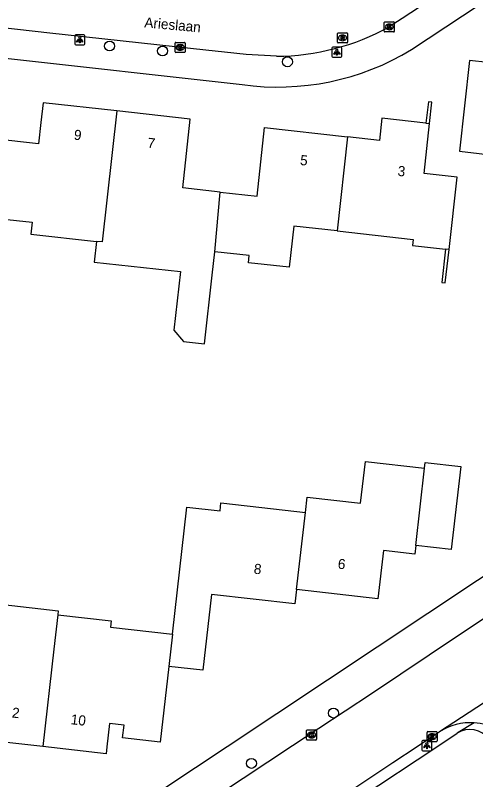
# Model space of a CAD drawing. Extents: x 162398 to 163643, y 386453 to 387397.
# Drawn here: x 163009.8 to 163055.2, y 386746.7 to 386822.3 of the extents above; entities that cross this region are included whole.
import ezdxf

# ---------------------------------------------------------------- set-up
doc = ezdxf.new("R2010")
doc.units = 0
for name, color, linetype in [('IMGEO_Boom', 7, 'Continuous'), ('IMGEO_Kolk', 7, 'Continuous'), ('IMGEO_Lichtpunt', 7, 'Continuous'), ('IMGEO_Muur', 7, 'Continuous'), ('IMGEO_Openbare_ruimte_label', 7, 'Continuous'), ('IMGEO_Pand', 7, 'Continuous'), ('IMGEO_Pand_nummerreeks', 7, 'Continuous'), ('IMGEO_Rijbaan_lokaal_gesloten', 7, 'Continuous'), ('IMGEO_Rijbaan_lokaal_open', 7, 'Continuous'), ('IMGEO_Rioolput', 7, 'Continuous'), ('IMGEO_Voetpad_open', 7, 'Continuous')]:
    doc.layers.add(name, color=color, linetype=linetype)

msp = doc.modelspace()

# ---------------------------------------------------------------- linework, layer by layer
at = {"layer": 'IMGEO_Boom'}
for centre in [(163019.068, 386819.272), (163024.298, 386818.785), (163036.636, 386817.714), (163041.181, 386753.326), (163033.082, 386748.352)]:
    msp.add_circle(centre, 0.489, dxfattribs=at)
at = {"layer": 'IMGEO_Kolk'}
for p, q in [((163046.192, 386820.738), (163046.192, 386821.59)), ((163046.267, 386821.664), (163047.119, 386821.664)), ((163046.68, 386821.444), (163046.705, 386821.444)), ((163047.193, 386821.59), (163047.193, 386820.738)), ((163047.119, 386820.664), (163046.267, 386820.664)), ((163046.703, 386820.884), (163046.678, 386820.884)), ((163025.537, 386818.707), (163025.537, 386819.559)), ((163025.612, 386819.633), (163026.464, 386819.633)), ((163026.025, 386819.413), (163026.05, 386819.413)), ((163026.538, 386819.559), (163026.538, 386818.707)), ((163026.048, 386818.853), (163026.023, 386818.853)), ((163026.464, 386818.633), (163025.612, 386818.633)), ((163038.52, 386750.737), (163038.52, 386751.589)), ((163038.595, 386751.663), (163039.447, 386751.663)), ((163039.008, 386751.443), (163039.033, 386751.443)), ((163039.521, 386751.589), (163039.521, 386750.737)), ((163050.426, 386750.569), (163050.426, 386751.421)), ((163050.501, 386751.495), (163051.353, 386751.495)), ((163051.427, 386751.421), (163051.427, 386750.569)), ((163039.447, 386750.663), (163038.595, 386750.663)), ((163039.031, 386750.883), (163039.006, 386750.883)), ((163050.937, 386750.715), (163050.912, 386750.715)), ((163050.914, 386751.275), (163050.939, 386751.275)), ((163051.353, 386750.495), (163050.501, 386750.495))]:
    msp.add_line(p, q, dxfattribs=at)
for points in [[(163046.192, 386820.738), (163046.192, 386821.59)], [(163046.267, 386821.664), (163047.119, 386821.664)], [(163046.513, 386821.364), (163046.636, 386821.364), (163046.636, 386821.213), (163046.766, 386821.364), (163046.93, 386821.364), (163046.784, 386821.213), (163046.937, 386820.964), (163046.785, 386820.964), (163046.7, 386821.128), (163046.636, 386821.061), (163046.636, 386820.964), (163046.513, 386820.964), (163046.513, 386821.364)], [(163047.193, 386821.59), (163047.193, 386820.738)], [(163047.119, 386820.664), (163046.267, 386820.664)], [(163025.537, 386818.707), (163025.537, 386819.559)], [(163025.612, 386819.633), (163026.464, 386819.633)], [(163026.538, 386819.559), (163026.538, 386818.707)], [(163025.858, 386819.333), (163025.981, 386819.333), (163025.981, 386819.182), (163026.111, 386819.333), (163026.275, 386819.333), (163026.129, 386819.182), (163026.282, 386818.933), (163026.13, 386818.933), (163026.045, 386819.097), (163025.981, 386819.03), (163025.981, 386818.933), (163025.858, 386818.933), (163025.858, 386819.333)], [(163026.464, 386818.633), (163025.612, 386818.633)], [(163038.52, 386750.737), (163038.52, 386751.589)], [(163038.595, 386751.663), (163039.447, 386751.663)], [(163039.521, 386751.589), (163039.521, 386750.737)], [(163050.426, 386750.569), (163050.426, 386751.421)], [(163050.501, 386751.495), (163051.353, 386751.495)], [(163051.427, 386751.421), (163051.427, 386750.569)], [(163039.447, 386750.663), (163038.595, 386750.663)], [(163038.841, 386751.363), (163038.964, 386751.363), (163038.964, 386751.212), (163039.094, 386751.363), (163039.258, 386751.363), (163039.112, 386751.212), (163039.265, 386750.963), (163039.113, 386750.963), (163039.028, 386751.127), (163038.964, 386751.06), (163038.964, 386750.963), (163038.841, 386750.963), (163038.841, 386751.363)], [(163050.747, 386751.195), (163050.87, 386751.195), (163050.87, 386751.044), (163051, 386751.195), (163051.164, 386751.195), (163051.018, 386751.044), (163051.171, 386750.795), (163051.019, 386750.795), (163050.934, 386750.959), (163050.87, 386750.892), (163050.87, 386750.795), (163050.747, 386750.795), (163050.747, 386751.195)], [(163051.353, 386750.495), (163050.501, 386750.495)]]:
    msp.add_lwpolyline(points, dxfattribs=at)
for centre, start, end in [((163046.269, 386821.588), 91.55205, 178.44795), ((163046.269, 386821.588), 91.55205, 178.44795), ((163047.117, 386821.588), 1.55205, 88.44795), ((163047.117, 386821.588), 1.55205, 88.44795), ((163046.269, 386820.74), 181.55205, 268.44795), ((163046.269, 386820.74), 181.55205, 268.44795), ((163047.117, 386820.74), 271.55205, 358.44795), ((163047.117, 386820.74), 271.55205, 358.44795), ((163025.614, 386819.557), 91.55205, 178.44795), ((163025.614, 386819.557), 91.55205, 178.44795), ((163026.462, 386819.557), 1.55205, 88.44795), ((163026.462, 386819.557), 1.55205, 88.44795), ((163025.614, 386818.709), 181.55205, 268.44795), ((163025.614, 386818.709), 181.55205, 268.44795), ((163026.462, 386818.709), 271.55205, 358.44795), ((163026.462, 386818.709), 271.55205, 358.44795), ((163038.597, 386751.587), 91.55205, 178.44795), ((163038.597, 386751.587), 91.55205, 178.44795), ((163039.445, 386751.587), 1.55205, 88.44795), ((163039.445, 386751.587), 1.55205, 88.44795), ((163050.503, 386751.419), 91.55205, 178.44795), ((163050.503, 386751.419), 91.55205, 178.44795), ((163051.351, 386751.419), 1.55205, 88.44795), ((163051.351, 386751.419), 1.55205, 88.44795), ((163038.597, 386750.739), 181.55205, 268.44795), ((163038.597, 386750.739), 181.55205, 268.44795), ((163039.445, 386750.739), 271.55205, 358.44795), ((163039.445, 386750.739), 271.55205, 358.44795), ((163050.503, 386750.571), 181.55205, 268.44795), ((163050.503, 386750.571), 181.55205, 268.44795), ((163051.351, 386750.571), 271.55205, 358.44795), ((163051.351, 386750.571), 271.55205, 358.44795)]:
    msp.add_arc(centre, 0.0765, start, end, dxfattribs=at)
for centre, major_axis, ratio, start_param, end_param in [((163046.679, 386821.164), (-0.387, 0.002), 0.722429, 4.712389, 7.853982), ((163046.704, 386821.164), (-0.39, 0.002), 0.717154, 1.570796, 4.712389), ((163026.024, 386819.133), (-0.387, 0.002), 0.722429, 4.712389, 7.853982), ((163026.049, 386819.133), (-0.39, 0.002), 0.717154, 1.570796, 4.712389), ((163039.007, 386751.163), (-0.387, 0.002), 0.722429, 4.712389, 7.853982), ((163039.032, 386751.163), (-0.39, 0.002), 0.717154, 1.570796, 4.712389), ((163050.913, 386750.995), (-0.387, 0.002), 0.722429, 4.712389, 7.853982), ((163050.938, 386750.995), (-0.39, 0.002), 0.717154, 1.570796, 4.712389)]:
    msp.add_ellipse(centre, major_axis=major_axis, ratio=ratio, start_param=start_param, end_param=end_param, dxfattribs=at)
at = {"layer": 'IMGEO_Lichtpunt'}
for p, q in [((163015.629, 386820.287), (163015.629, 386819.48)), ((163015.629, 386820.287), (163015.629, 386819.48)), ((163016.531, 386820.382), (163015.723, 386820.382)), ((163016.531, 386820.382), (163015.723, 386820.382)), ((163016.625, 386819.48), (163016.625, 386820.287)), ((163016.625, 386819.48), (163016.625, 386820.287)), ((163015.723, 386819.386), (163016.531, 386819.386)), ((163015.723, 386819.386), (163016.531, 386819.386)), ((163041.017, 386819.068), (163041.017, 386818.261)), ((163041.017, 386819.068), (163041.017, 386818.261)), ((163041.919, 386819.163), (163041.111, 386819.163)), ((163041.919, 386819.163), (163041.111, 386819.163)), ((163042.013, 386818.261), (163042.013, 386819.068)), ((163042.013, 386818.261), (163042.013, 386819.068)), ((163041.111, 386818.167), (163041.919, 386818.167)), ((163041.111, 386818.167), (163041.919, 386818.167)), ((163049.911, 386750.508), (163049.911, 386749.701)), ((163049.911, 386750.508), (163049.911, 386749.701)), ((163050.813, 386750.603), (163050.005, 386750.603)), ((163050.813, 386750.603), (163050.005, 386750.603)), ((163050.907, 386749.701), (163050.907, 386750.508)), ((163050.907, 386749.701), (163050.907, 386750.508)), ((163050.005, 386749.607), (163050.813, 386749.607)), ((163050.005, 386749.607), (163050.813, 386749.607))]:
    msp.add_line(p, q, dxfattribs=at)
for points in [[(163016.003, 386819.951), (163016.042, 386819.923), (163015.854, 386819.661), (163015.816, 386819.688), (163016.003, 386819.951)], [(163016.105, 386819.903), (163016.152, 386819.903), (163016.152, 386819.581), (163016.105, 386819.581), (163016.105, 386819.903)], [(163016.215, 386819.923), (163016.253, 386819.95), (163016.44, 386819.688), (163016.401, 386819.66), (163016.215, 386819.923)], [(163041.391, 386818.732), (163041.43, 386818.704), (163041.242, 386818.442), (163041.204, 386818.469), (163041.391, 386818.732)], [(163041.493, 386818.684), (163041.54, 386818.684), (163041.54, 386818.362), (163041.493, 386818.362), (163041.493, 386818.684)], [(163041.603, 386818.704), (163041.641, 386818.731), (163041.828, 386818.469), (163041.789, 386818.441), (163041.603, 386818.704)], [(163050.285, 386750.172), (163050.324, 386750.144), (163050.136, 386749.882), (163050.098, 386749.909), (163050.285, 386750.172)], [(163050.387, 386750.124), (163050.434, 386750.124), (163050.434, 386749.802), (163050.387, 386749.802), (163050.387, 386750.124)], [(163050.497, 386750.144), (163050.535, 386750.171), (163050.722, 386749.909), (163050.683, 386749.881), (163050.497, 386750.144)]]:
    msp.add_lwpolyline(points, dxfattribs=at)
for centre in [(163016.128, 386820.085), (163041.516, 386818.866), (163050.41, 386750.306)]:
    msp.add_circle(centre, 0.0994, dxfattribs=at)
for centre, start, end in [((163015.723, 386820.287), 90, 180), ((163015.723, 386820.287), 90, 180), ((163016.531, 386820.287), 0, 90), ((163016.531, 386820.287), 0, 90), ((163015.723, 386819.48), 180, 270), ((163015.723, 386819.48), 180, 270), ((163016.531, 386819.48), 270, 0), ((163016.531, 386819.48), 270, 360), ((163041.111, 386819.068), 90, 180), ((163041.111, 386819.068), 90, 180), ((163041.919, 386819.068), 0, 90), ((163041.919, 386819.068), 0, 90), ((163041.111, 386818.261), 180, 270), ((163041.111, 386818.261), 180, 270), ((163041.919, 386818.261), 270, 0), ((163041.919, 386818.261), 270, 360), ((163050.005, 386750.508), 90, 180), ((163050.005, 386750.508), 90, 180), ((163050.813, 386750.508), 0, 90), ((163050.813, 386750.508), 0, 90), ((163050.005, 386749.701), 180, 270), ((163050.005, 386749.701), 180, 270), ((163050.813, 386749.701), 270, 0), ((163050.813, 386749.701), 270, 360)]:
    msp.add_arc(centre, 0.0946, start, end, dxfattribs=at)
at = {"layer": 'IMGEO_Muur'}
for points in [[(163050.672, 386811.602), (163050.908, 386813.721), (163050.555, 386813.76), (163050.319, 386811.641)], [(163052.257, 386799.205), (163051.89, 386795.908), (163052.226, 386795.871), (163052.593, 386799.168)]]:
    msp.add_lwpolyline(points, dxfattribs=at)
at = {"layer": 'IMGEO_Pand'}
for points in [[(163066.327, 386819.722), (163058.593, 386820.582), (163058.245, 386817.455), (163054.632, 386817.856), (163054.132, 386813.363), (163053.632, 386808.864), (163057.516, 386808.432), (163057.789, 386810.893), (163065.254, 386810.063)], [(163019.775, 386812.85), (163012.505, 386813.659), (163012.288, 386811.705), (163012.052, 386809.588), (163007.606, 386810.082), (163007.27, 386807.057)], [(163019.775, 386812.85), (163018.332, 386799.903), (163017.79, 386799.963)], [(163030.005, 386804.84), (163026.29, 386805.253), (163027.045, 386812.042), (163019.775, 386812.85)], [(163050.319, 386811.641), (163045.955, 386812.126), (163045.712, 386809.946), (163042.58, 386810.294)], [(163030.005, 386804.84), (163033.631, 386804.437), (163034.384, 386811.205), (163042.58, 386810.294)], [(163052.593, 386799.168), (163053.388, 386806.32), (163050.125, 386806.683), (163050.672, 386811.602)], [(163050.319, 386811.641), (163050.672, 386811.602)], [(163042.58, 386810.294), (163041.544, 386800.986)], [(163029.462, 386798.929), (163030.005, 386804.84)], [(163006.748, 386802.369), (163011.436, 386801.848), (163011.307, 386800.683), (163017.79, 386799.963)], [(163041.544, 386800.986), (163037.264, 386801.462), (163036.812, 386797.398), (163032.789, 386797.846), (163032.867, 386798.55), (163029.462, 386798.929)], [(163041.544, 386800.986), (163049.062, 386800.15), (163048.997, 386799.567), (163052.257, 386799.205)], [(163017.79, 386799.963), (163017.563, 386797.918), (163026.073, 386796.972), (163025.428, 386791.171), (163026.374, 386790.071), (163028.451, 386789.84), (163029.206, 386796.623), (163029.462, 386798.929)], [(163052.593, 386799.168), (163052.257, 386799.205)], [(163038.409, 386773.163), (163038.581, 386774.671), (163043.866, 386774.067), (163044.339, 386778.203), (163050.183, 386777.535)], [(163050.183, 386777.535), (163050.247, 386778.097), (163053.753, 386777.697), (163052.816, 386769.493), (163049.306, 386769.894)], [(163049.306, 386769.894), (163050.183, 386777.535)], [(163025.28, 386761.115), (163026.716, 386773.684), (163029.982, 386773.311), (163030.074, 386774.115), (163035.259, 386773.523), (163038.409, 386773.163)], [(163037.541, 386765.536), (163038.409, 386773.163)], [(163049.306, 386769.894), (163049.208, 386769.033), (163046.119, 386769.385), (163045.574, 386764.618), (163037.541, 386765.536)], [(163037.541, 386765.536), (163037.378, 386764.113), (163029.133, 386765.055), (163028.276, 386757.554), (163024.923, 386757.937)], [(163012.47, 386750.008), (163006.213, 386750.723), (163006.545, 386753.632), (163001.291, 386754.232), (163001.859, 386759.2), (163002.375, 386763.72), (163008.45, 386763.025), (163008.567, 386764.05), (163014.004, 386763.429), (163013.961, 386763.046)], [(163013.961, 386763.046), (163013.572, 386759.652), (163012.47, 386750.008)], [(163013.961, 386763.046), (163019.238, 386762.443), (163019.166, 386761.814), (163025.28, 386761.115)], [(163025.28, 386761.115), (163024.923, 386757.937)], [(163024.923, 386757.937), (163024.067, 386750.448), (163020.358, 386750.871), (163020.501, 386752.127), (163019.068, 386752.291), (163018.806, 386750), (163018.725, 386749.294), (163012.47, 386750.008)]]:
    msp.add_lwpolyline(points, dxfattribs=at)
at = {"layer": 'IMGEO_Rijbaan_lokaal_gesloten'}
for points in [[(163018.704, 386737.897), (163020.532, 386739.148), (163021.049, 386739.492), (163022.823, 386740.671), (163027.385, 386743.673), (163037.12, 386750.107), (163044.946, 386755.247), (163053.527, 386761.018), (163084.016, 386781.282)], [(163065.539, 386760.542), (163051.663, 386751.486)], [(163051.663, 386751.486), (163051.609, 386751.451), (163051.556, 386751.416), (163049.437, 386750), (163047.031, 386748.398), (163043.288, 386745.904), (163024.659, 386733.665), (163022.574, 386732.192)]]:
    msp.add_lwpolyline(points, dxfattribs=at)
at = {"layer": 'IMGEO_Rijbaan_lokaal_open'}
for points in [[(163063.954, 386832.5), (163059.032, 386829.268), (163055.219, 386826.764), (163052.249, 386824.813), (163047.956, 386821.995), (163046.696, 386821.167)], [(163035.545, 386818.259), (163032.562, 386818.421), (163027.362, 386818.989), (163013.168, 386820.54), (163004.709, 386821.506)]]:
    msp.add_lwpolyline(points, dxfattribs=at)
for centre, radius, start, end in [((163035.335, 386841.898), 23.64, 270.50883, 298.72371), ((163054.725, 386746.675), 5.703, 86.3569, 122.47029), ((163054.72, 386746.67), 5.708, 39.54324, 86.30859)]:
    msp.add_arc(centre, radius, start, end, dxfattribs=at)
at = {"layer": 'IMGEO_Rioolput'}
for p, q in [((163041.577, 386819.654), (163041.577, 386820.506)), ((163041.652, 386820.58), (163042.504, 386820.58)), ((163042.065, 386820.36), (163042.09, 386820.36)), ((163042.578, 386820.506), (163042.578, 386819.654)), ((163042.504, 386819.58), (163041.652, 386819.58)), ((163042.088, 386819.8), (163042.063, 386819.8))]:
    msp.add_line(p, q, dxfattribs=at)
for points in [[(163041.577, 386819.654), (163041.577, 386820.506)], [(163041.652, 386820.58), (163042.504, 386820.58)], [(163042.166, 386820.278), (163041.914, 386820.28), (163041.914, 386819.88)], [(163042.092, 386820.199), (163042.038, 386820.199), (163042.038, 386820.118)], [(163042.578, 386820.506), (163042.578, 386819.654)], [(163042.504, 386819.58), (163041.652, 386819.58)], [(163041.914, 386819.88), (163042.038, 386819.88), (163042.038, 386820.042), (163042.049, 386820.042)], [(163042.038, 386820.118), (163042.09, 386820.118)], [(163042.096, 386820.013), (163042.167, 386819.88), (163042.307, 386819.88), (163042.242, 386820.006)]]:
    msp.add_lwpolyline(points, dxfattribs=at)
for centre, radius, start, end in [((163041.654, 386820.504), 0.0765, 91.55205, 178.44795), ((163041.654, 386820.504), 0.0765, 91.55205, 178.44795), ((163042.098, 386820.103), 0.0964, 77.00612, 93.18647), ((163042.112, 386820.16), 0.0378, 276.66336, 79.67722), ((163042.165, 386820.168), 0.109, 350.36119, 89.41601), ((163042.502, 386820.504), 0.0765, 1.55205, 88.44795), ((163042.502, 386820.504), 0.0765, 1.55205, 88.44795), ((163041.654, 386819.656), 0.0765, 181.55205, 268.44795), ((163041.654, 386819.656), 0.0765, 181.55205, 268.44795), ((163042.048, 386819.989), 0.0533, 26.02933, 88.69889), ((163042.074, 386820.307), 0.19, 274.7715, 282.96867), ((163042.163, 386820.168), 0.112, 277.58423, 350.98172), ((163042.147, 386819.953), 0.108, 29.51342, 73.79051), ((163042.502, 386819.656), 0.0765, 271.55205, 358.44795), ((163042.502, 386819.656), 0.0765, 271.55205, 358.44795)]:
    msp.add_arc(centre, radius, start, end, dxfattribs=at)
for centre, major_axis, ratio, start_param, end_param in [((163042.064, 386820.08), (-0.387, 0.002), 0.722429, 4.712389, 7.853982), ((163042.089, 386820.08), (-0.39, 0.002), 0.717154, 1.570796, 4.712389)]:
    msp.add_ellipse(centre, major_axis=major_axis, ratio=ratio, start_param=start_param, end_param=end_param, dxfattribs=at)
at = {"layer": 'IMGEO_Voetpad_open'}
for points in [[(163048.892, 386818.913), (163067.287, 386831.119)], [(163008.483, 386818.116), (163032.153, 386815.458)], [(163090.874, 386798.95), (163094.938, 386792.726), (163030.691, 386750), (163014.944, 386739.528)], [(163055.087, 386752.366), (163053.489, 386751.42), (163053.391, 386751.338)], [(163023.952, 386731.758), (163043.727, 386744.911), (163051.379, 386750), (163053.391, 386751.338)]]:
    msp.add_lwpolyline(points, dxfattribs=at)
for centre, radius, start, end in [((163035.667, 386840.709), 25.494, 262.07687, 301.24776), ((163054.648, 386749.448), 2.27, 33.80839, 123.62784)]:
    msp.add_arc(centre, radius, start, end, dxfattribs=at)

# ---------------------------------------------------------------- texts
at = {"layer": 'IMGEO_Openbare_ruimte_label'}
msp.add_text('Arieslaan', height=1, rotation=354.77964, dxfattribs=at).set_placement((163022.478, 386821.128))
at = {"layer": 'IMGEO_Pand_nummerreeks'}
for s, rotation, p in [('9', 353.65163, (163015.503, 386810.025)), ('7', 353.65736, (163022.774, 386809.217)), ('5', 353.6506, (163037.845, 386807.52)), ('3', 353.65736, (163047.481, 386806.449)), ('8', 353.47974, (163033.272, 386767.118)), ('6', 353.4912, (163041.569, 386767.611)), ('2', 353.48403, (163009.388, 386752.897)), ('10', 353.4849, (163015.192, 386752.233))]:
    msp.add_text(s, height=1, rotation=rotation, dxfattribs=at).set_placement(p)

doc.saveas('drawing.dxf')
